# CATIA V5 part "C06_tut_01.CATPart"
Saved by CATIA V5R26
Part number: Part1
Bounding box of the stored display mesh (mm): x -101.061 to 0, y -66 to 66, z 0 to 105.937
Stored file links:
  D:\_Deepak\CATIA\CATIA V5 2015 Parts Files\Tutorial Files\Tutorials\c06_catia_v5_6r2015_tut\C06_tut_01.CATPart
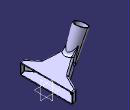
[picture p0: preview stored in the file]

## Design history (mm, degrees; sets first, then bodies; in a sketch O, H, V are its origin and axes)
Body1 (main body)
  Sketch1 on zx-plane, origin (0, 0, 0), H (-1, 0, 0), V (0, 0, 1)
    line L1 (0, 0) -> (0, 28)
    point P1 (0, 28)
    line L2 (0, 28) -> (61.837, 58.1599)
    line L3 (61.837, 58.1599) -> (61.837, 30.1599)
    line L4 (61.837, 30.1599) -> (0, 0)
    distance P1 H = 28
    angle L4 H = 26
    length L4 = 68.8
    vertical: L1 V, L3 V
    parallelism: L2 L4
  Pad1: profile Sketch1, direction (0, 1, 0), length 66, mirrored extent
  Sketch2 on face of Pad1 from Sketch1.L2, origin (11.0322, 0, 22.6193), H (0, 1, 0), V (-0.8988, 0, 0.4384)
    point P1 (-66, 12.2744)
    line L1 (-66, 12.2744) -> (-65.4759, 22.2744)
    line L2 (-65.4759, 22.2744) -> (-33, 37.2744)
    point P3 (-33, 37.2744)
    line L3 (-33, 37.2744) -> (-10.1992, 81.0744)
    line L4 (-10.1992, 81.0744) -> (10.1992, 81.0744)
    line L5 (10.1992, 81.0744) -> (33, 37.2744)
    point P6 (33, 37.2744)
    line L6 (33, 37.2744) -> (65.4759, 22.2744)
    point P7 (65.4759, 22.2744)
    line L7 (65.4759, 22.2744) -> (66, 12.2744)
    point P8 (66, 12.2744)
    line L8 (66, 12.2744) -> (-66, 12.2744)
    reference projected point E1 (66, 12.2744) from vertex [face of Pad1 from Sketch1.L1 | end face of Pad1 | face of Pad1 from Sketch1.L2]
    reference projected point E2 (-66, 12.2744) from vertex [face of Pad1 from Sketch1.L1 | start face of Pad1 | face of Pad1 from Sketch1.L2]
    reference projected line E3 (66, 81.0744) -> (66, 12.2744) from edge [face of Pad1 from Sketch1.L2 | end face of Pad1]
    reference projected line E4 (-66, 81.0744) -> (66, 81.0744) from edge [face of Pad1 from Sketch1.L2 | face of Pad1 from Sketch1.L3]
    angle L7 E3 = 3
    angle L3 L5 = 55
    distance P3 P6 = 66
    distance P7 L8 = 10
    distance P6 L8 = 25
    horizontal: L4 H, L8 H
    coincidence: P8 E1, P1 E2, L4 E4
    symmetry: L7 L1 V, L6 L2 V, L3 L5 V
  Pocket1: profile Sketch2, direction along edge [face of Pad1 from Sketch1.L1 | end face of Pad1], through (limit type 6), outer side
  Sketch3 on zx-plane, origin (0, 0, 0), H (-1, 0, 0), V (0, 0, 1)
    line L1 (61.837, 44.1599) -> (86.4446, 99.4294)
    point P1 (61.837, 44.1599)
    point P2 (86.4446, 99.4294)
    reference projected line E1 (22.4699, 10.9593) -> (61.837, 30.1599) from edge [face of Pad1 from Sketch1.L4 | face of Pocket1 from Sketch2.L5]
    reference projected line E2 (61.837, 58.1599) -> (61.837, 30.1599) from edge [face of Pocket1 from Sketch2.L5 | face of Pad1 from Sketch1.L3]
    reference projected point E3 (61.837, 58.1599) from vertex [face of Pocket1 from Sketch2.L5 | face of Pad1 from Sketch1.L2 | face of Pad1 from Sketch1.L3]
    angle L1 E1 = 140
    distance P1 E3 = 14
    length L1 = 60.5
    coincidence: P1 E2
  Plane1: type Normal, Curve Sketch3, RefPoint Sketch3.P2, Ratio 0
  Sketch4 on Plane1, origin (-51.2462, 0, 115.1008), H (0, -1, 0), V (0.9135, 0, 0.4067)
    circle A1 centre (0, -38.5295) radius 16
    point P1 (0, -38.5295)
    reference projected point E1 (0, -38.5295) from Sketch3.P2
    radius A1 = 16
    coincidence: P1 V, E1 P1
  Pad2: profile Sketch4, direction (-0.4067, 0, 0.9135), length 0, opposite side up to xy-plane
  Draft1: Angle -2, Neutral end face of Pad2, PullDir end face of Pad2, SupportToDraft face of Pad2 from Sketch4.A1
  Sketch5 on face of Pad1 from Sketch1.L4, origin (0, 0, 0), H (0, -1, 0), V (-0.8988, 0, 0.4384)
    line L1 (-57.0234, 118.908) -> (69.9188, 118.908)
    line L2 (69.9188, 118.908) -> (69.9188, 16.5882)
    line L3 (69.9188, 16.5882) -> (-57.0234, 16.5882)
    line L4 (-57.0234, 16.5882) -> (-57.0234, 118.908)
    horizontal: L1 H, L3 H
    vertical: L2 V, L4 V
  Pocket2: profile Sketch5, direction (-0.4384, 0, -0.8988), through (limit type 6)
  Fillet1: radius 12, on edge [face of Pad2 from Sketch4.A1 | face of Pad1 from Sketch1.L2]; edge [face of Pad2 from Sketch4.A1 | face of Pocket1 from Sketch2.L5]; edge [face of Pad2 from Sketch4.A1 | face of Pocket1 from Sketch2.L3]
  Fillet2: radius 3, on edge [face of Pad1 from Sketch1.L2 | face of Pocket1 from Sketch2.L5]; edge [face of Pad1 from Sketch1.L2 | face of Pocket1 from Sketch2.L3]; edge [face of Pocket1 from Sketch2.L2 | face of Pad1 from Sketch1.L2]; edge [face of Pocket1 from Sketch2.L1 | face of Pad1 from Sketch1.L2]; edge [face of Pocket1 from Sketch2.L7 | face of Pad1 from Sketch1.L2]; edge [face of Pocket1 from Sketch2.L6 | face of Pad1 from Sketch1.L2]; edge [face of Pocket1 from Sketch2.L6 | face of Pocket1 from Sketch2.L5]; edge [face of Pocket1 from Sketch2.L7 | face of Pocket1 from Sketch2.L6]; edge [face of Pocket1 from Sketch2.L6 | face of Pocket2]; edge [face of Pocket2 | face of Pocket1 from Sketch2.L7]; edge [face of Pocket1 from Sketch2.L5 | face of Pocket2]; edge [face of Pocket2 | face of Pocket1 from Sketch2.L2]; edge [face of Pocket1 from Sketch2.L1 | face of Pocket2]; edge [face of Pocket1 from Sketch2.L2 | face of Pocket1 from Sketch2.L1]; edge [face of Pocket1 from Sketch2.L3 | face of Pocket1 from Sketch2.L2]
  Shell1: ExtOffset 0, Face (end face of Pad2; face of Pad1 from Sketch1.L1), IntOffset 2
